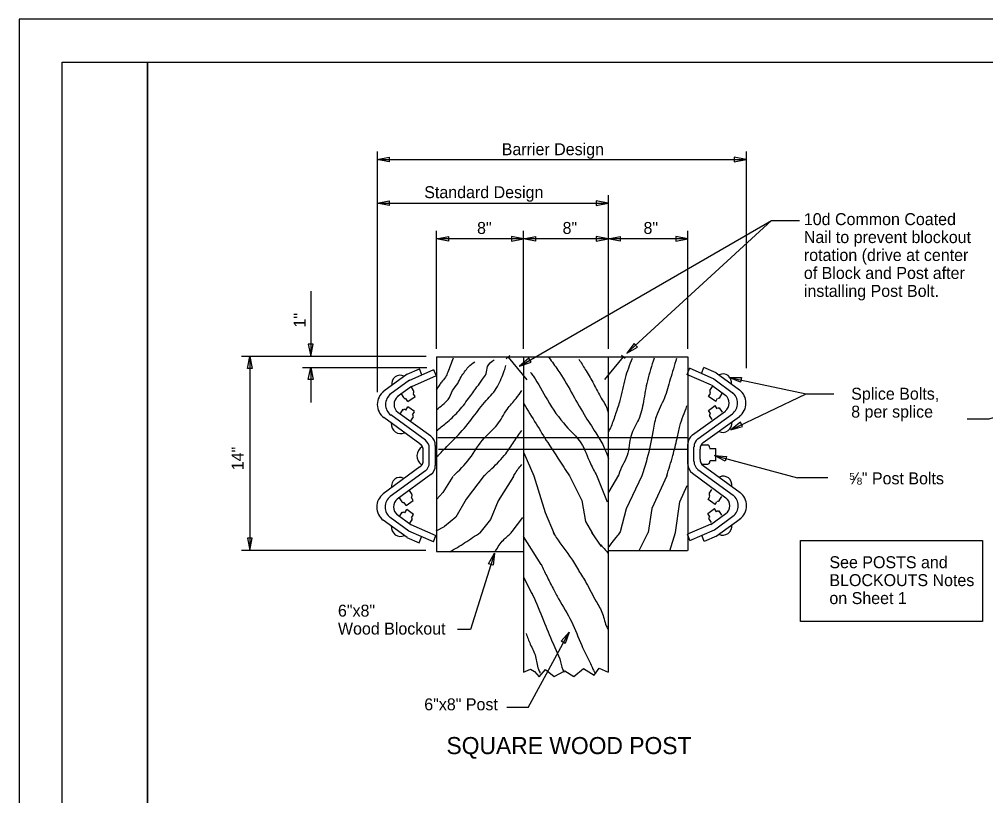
# Model space of a CAD drawing. Extents: x 0 to 34, y 0 to 22.
# Drawn here: x 0 to 11.31, y 12.91 to 22 of the extents above; entities that cross this region are included whole.
import ezdxf

# ---------------------------------------------------------------- set-up
doc = ezdxf.new("R2010")
doc.units = 0
for name, color, linetype in [('SH_Border', 7, 'Continuous'), ('SH_Cut_Line', 7, 'Continuous'), ('ST_Details', 7, 'Continuous'), ('ST_Text', 7, 'Continuous')]:
    doc.layers.add(name, color=color, linetype=linetype)

msp = doc.modelspace()

# ---------------------------------------------------------------- linework, layer by layer
at = {"layer": 'SH_Border'}
for points in [[(0.5, 21.5), (1.5, 21.5), (1.5, 0.5), (0.5, 0.5)], [(1.5, 21.5), (33.5, 21.5), (33.5, 0.5), (1.5, 0.5)]]:
    msp.add_lwpolyline(points, close=True, dxfattribs=at)
at = {"layer": 'SH_Cut_Line'}
msp.add_lwpolyline([(0, 0), (34, 0), (34, 22), (0, 22)], close=True, dxfattribs=at)
at = {"layer": 'ST_Details'}
for p, q in [((4.883, 18.048), (7.822, 18.048)), ((4.883, 18.048), (4.883, 15.767)), ((5.739, 18.063), (5.697, 18.026)), ((5.72, 18.044), (5.941, 17.779)), ((5.901, 18.048), (5.901, 14.354)), ((7.068, 18.049), (6.847, 17.784)), ((6.893, 18.048), (6.893, 14.354)), ((7.049, 18.068), (7.091, 18.031)), ((7.822, 18.048), (7.822, 15.78)), ((4.538, 17.845), (4.682, 17.908)), ((4.563, 17.772), (4.852, 17.898)), ((4.709, 17.838), (4.682, 17.907)), ((4.878, 17.828), (4.851, 17.897)), ((7.816, 17.843), (7.843, 17.913)), ((8.131, 17.787), (7.842, 17.914)), ((7.984, 17.853), (8.012, 17.922)), ((8.156, 17.86), (8.012, 17.923)), ((4.538, 17.845), (4.265, 17.645)), ((4.565, 17.773), (4.335, 17.605)), ((4.592, 17.701), (4.881, 17.828)), ((8.102, 17.717), (7.812, 17.843)), ((8.129, 17.789), (8.359, 17.62)), ((8.156, 17.86), (8.429, 17.66)), ((4.591, 17.701), (4.424, 17.579)), ((4.615, 17.653), (4.585, 17.7)), ((8.083, 17.655), (8.113, 17.702)), ((8.103, 17.716), (8.27, 17.594)), ((4.5, 17.57), (4.471, 17.616)), ((4.548, 17.524), (4.525, 17.56)), ((4.548, 17.524), (4.631, 17.583)), ((4.631, 17.583), (4.608, 17.618)), ((8.067, 17.585), (8.09, 17.62)), ((8.15, 17.526), (8.067, 17.585)), ((8.15, 17.526), (8.173, 17.562)), ((8.198, 17.572), (8.227, 17.618)), ((4.463, 17.385), (4.494, 17.435)), ((4.523, 17.425), (4.547, 17.464)), ((4.626, 17.406), (4.547, 17.463)), ((8.065, 17.421), (8.144, 17.478)), ((8.089, 17.383), (8.065, 17.42)), ((8.168, 17.44), (8.143, 17.479)), ((8.228, 17.4), (8.196, 17.45)), ((4.689, 17.028), (4.266, 17.336)), ((4.752, 17.073), (4.348, 17.367)), ((4.815, 17.118), (4.431, 17.398)), ((4.581, 17.299), (4.612, 17.347)), ((4.601, 17.367), (4.625, 17.405)), ((7.879, 17.133), (8.263, 17.413)), ((7.942, 17.088), (8.346, 17.382)), ((8.005, 17.043), (8.428, 17.351)), ((8.11, 17.314), (8.079, 17.362)), ((4.898, 17.102), (7.822, 17.102)), ((4.798, 16.807), (4.798, 16.98)), ((4.869, 16.777), (4.869, 17.01)), ((4.905, 16.966), (7.819, 16.966)), ((7.825, 16.792), (7.825, 17.025)), ((7.896, 16.822), (7.896, 16.995)), ((7.967, 16.851), (7.967, 16.966)), ((7.982, 17.016), (8.054, 17.016)), ((8.078, 16.975), (8.15, 16.975)), ((8.151, 16.835), (8.151, 16.974)), ((4.727, 16.836), (4.727, 16.95)), ((4.798, 16.888), (4.798, 16.899)), ((5.903, 16.922), (6.021, 16.653)), ((7.896, 16.903), (7.896, 16.914)), ((7.939, 16.964), (7.939, 16.964)), ((4.689, 16.759), (4.259, 16.444)), ((7.984, 16.791), (8.046, 16.791)), ((8.005, 16.774), (8.435, 16.459)), ((8.08, 16.835), (8.154, 16.835)), ((4.752, 16.714), (4.341, 16.413)), ((4.815, 16.669), (4.424, 16.382)), ((6.754, 16.662), (6.878, 16.351)), ((7.014, 16.662), (6.895, 16.465)), ((7.878, 16.685), (8.27, 16.397)), ((7.942, 16.73), (8.353, 16.428)), ((4.596, 16.435), (4.565, 16.482)), ((4.611, 16.365), (4.588, 16.4)), ((8.06, 16.378), (8.082, 16.414)), ((8.075, 16.448), (8.105, 16.495)), ((8.191, 16.366), (8.22, 16.411)), ((4.48, 16.352), (4.451, 16.398)), ((4.529, 16.306), (4.505, 16.342)), ((4.528, 16.306), (4.611, 16.365)), ((8.142, 16.32), (8.06, 16.378)), ((8.142, 16.319), (8.165, 16.355)), ((4.581, 16.082), (4.424, 16.197)), ((4.45, 16.18), (4.482, 16.23)), ((4.51, 16.22), (4.535, 16.259)), ((4.613, 16.201), (4.535, 16.259)), ((4.589, 16.163), (4.613, 16.2)), ((8.057, 16.214), (8.136, 16.272)), ((8.081, 16.176), (8.058, 16.213)), ((8.095, 16.085), (8.27, 16.212)), ((8.135, 16.023), (8.352, 16.181)), ((8.16, 16.233), (8.136, 16.272)), ((8.22, 16.193), (8.189, 16.243)), ((4.538, 15.931), (4.259, 16.135)), ((4.559, 16.007), (4.341, 16.166)), ((4.568, 16.094), (4.599, 16.142)), ((4.581, 16.083), (4.875, 15.955)), ((4.88, 16.01), (4.975, 16.061)), ((5.767, 16.001), (5.891, 16.167)), ((8.112, 16.098), (7.819, 15.97)), ((8.102, 16.107), (8.071, 16.155)), ((8.155, 15.947), (8.435, 16.15)), ((4.847, 15.881), (4.558, 16.008)), ((4.846, 15.881), (4.875, 15.955)), ((6.698, 15.992), (6.81, 15.827)), ((7.256, 15.78), (7.36, 15.992)), ((7.615, 15.776), (7.678, 15.992)), ((7.848, 15.897), (7.819, 15.97)), ((7.847, 15.897), (8.136, 16.023)), ((8.015, 15.885), (7.986, 15.958)), ((8.158, 15.947), (8.014, 15.885)), ((4.536, 15.932), (4.68, 15.869)), ((4.679, 15.87), (4.708, 15.942)), ((6.107, 15.617), (5.899, 15.943)), ((4.883, 15.767), (5.9, 15.767)), ((6.891, 15.78), (7.82, 15.78)), ((5.899, 15.469), (6, 15.276)), ((6.24, 14.705), (6.325, 14.51))]:
    msp.add_line(p, q, dxfattribs=at)
for points in [[(5.075, 16.645), (4.956, 16.461), (4.886, 16.382)], [(5.44, 16.657), (5.228, 16.382), (5.11, 16.171), (4.975, 16.061)], [(5.782, 16.647), (5.605, 16.36), (5.513, 16.145), (5.39, 15.988)], [(6.021, 16.653), (6.154, 16.224), (6.258, 15.974)], [(6.438, 16.653), (6.584, 16.364), (6.628, 16.119), (6.707, 15.979)], [(7.284, 16.653), (7.101, 16.268), (7.031, 15.997)], [(7.577, 16.653), (7.404, 16.272), (7.36, 15.992)], [(7.678, 15.992), (7.729, 16.351), (7.816, 16.54)], [(5.901, 14.354), (5.982, 14.392), (6.028, 14.362), (6.085, 14.3), (6.16, 14.388), (6.259, 14.305), (6.383, 14.37), (6.491, 14.305), (6.602, 14.397), (6.726, 14.322), (6.788, 14.401), (6.893, 14.354)]]:
    msp.add_lwpolyline(points, dxfattribs=at)
for centre, major_axis, start_param, end_param in [((4.458, 17.726), (0, -0.107), 2.687211, 4.851441), ((8.236, 17.741), (0, -0.107), 1.431744, 3.595974), ((4.366, 17.49), (0, -0.187), 3.747084, 5.680264), ((4.6, 17.64), (0, 0.0198), 3.70437, 5.352473), ((8.098, 17.642), (0, 0.0198), 0.930712, 2.578815), ((8.328, 17.506), (0, -0.187), 0.602921, 2.536101), ((4.428, 17.49), (0, -0.15), 3.747137, 5.680324), ((4.491, 17.491), (0, -0.112), 3.747102, 5.680297), ((4.513, 17.581), (0, -0.0195), 5.247458, 6.879592), ((8.185, 17.583), (0, -0.0195), 5.686779, 7.318912), ((8.203, 17.506), (0, -0.112), 0.602888, 2.536083), ((8.265, 17.506), (0, -0.15), 0.602861, 2.536048), ((4.507, 17.411), (0, 0.021), 5.452301, 7.118326), ((8.184, 17.426), (0, 0.021), 5.448045, 7.11407), ((4.592, 17.349), (0, 0.021), 4.196406, 5.73538), ((8.098, 17.364), (0, 0.021), 0.547805, 2.086779), ((4.461, 17.263), (0, -0.115), 4.640651, 6.714317), ((8.233, 17.278), (0, -0.115), 5.852054, 7.925719), ((4.745, 17.01), (0, 0.131), 4.712389, 5.680267), ((7.949, 17.025), (0, 0.131), 0.602918, 1.570796), ((8.002, 16.995), (0, 0.112), 0.602846, 1.570796), ((4.767, 16.888), (0, -0.12), 3.613765, 5.74142), ((4.639, 16.95), (0, 0.0937), 4.712389, 5.680377), ((4.692, 16.98), (0, 0.112), 4.712389, 5.68034), ((8.055, 16.966), (0, 0.0937), 0.602808, 1.570796), ((8.053, 16.986), (0, -0.0298), 2.729343, 3.43401), ((8.052, 16.985), (0, 0.03), 4.574534, 6.237266), ((8.053, 16.986), (0, -0.0298), 1.431351, 1.439211), ((4.639, 16.836), (0, -0.0937), 0.605563, 1.570796), ((4.692, 16.807), (0, -0.112), 0.605651, 1.570796), ((4.745, 16.777), (0, -0.131), 0.605566, 1.570796), ((7.949, 16.792), (0, -0.131), 4.712389, 5.677619), ((8.002, 16.822), (0, -0.112), 4.712389, 5.677535), ((8.055, 16.851), (0, -0.0937), 4.712389, 5.677623), ((8.051, 16.823), (0, -0.0326), 6.093782, 8.000338), ((4.455, 16.529), (0, -0.107), 2.687211, 4.851441), ((8.239, 16.544), (0, -0.107), 1.431744, 3.595974), ((4.359, 16.289), (0, -0.187), 3.747091, 5.68028), ((4.422, 16.289), (0, -0.15), 3.747115, 5.680355), ((4.58, 16.423), (0, 0.0198), 3.70437, 5.352473), ((8.091, 16.436), (0, 0.0198), 0.930712, 2.578815), ((8.272, 16.305), (0, -0.15), 0.602831, 2.53607), ((8.334, 16.305), (0, -0.187), 0.602905, 2.536094), ((4.484, 16.29), (0, -0.112), 3.747102, 5.680258), ((4.493, 16.363), (0, -0.0195), 5.247458, 6.879592), ((8.178, 16.376), (0, -0.0195), 5.686779, 7.318912), ((8.21, 16.305), (0, -0.112), 0.602927, 2.536083), ((4.494, 16.207), (0, 0.021), 5.452301, 7.118326), ((8.09, 16.157), (0, 0.021), 0.547805, 2.086779), ((8.176, 16.22), (0, 0.021), 5.448045, 7.11407), ((4.461, 16.06), (0, -0.115), 4.640651, 6.714317), ((4.58, 16.144), (0, 0.021), 4.196406, 5.73538), ((8.233, 16.075), (0, -0.115), 5.852054, 7.925719)]:
    msp.add_ellipse(centre, major_axis=major_axis, ratio=0.944544, start_param=start_param, end_param=end_param, dxfattribs=at)
for points in [[(5.078, 18.034), (5.015, 17.868), (4.986, 17.81), (4.942, 17.752), (4.913, 17.714), (4.88, 17.656)], [(4.884, 17.183), (4.993, 17.272), (5.131, 17.402), (5.258, 17.56), (5.356, 17.695), (5.422, 17.787), (5.462, 17.852), (5.48, 17.933), (5.557, 18.014)], [(4.884, 17.426), (4.953, 17.487), (5.019, 17.549), (5.069, 17.652), (5.131, 17.737), (5.171, 17.814), (5.211, 17.872), (5.255, 17.929), (5.33, 17.99)], [(6.198, 18.039), (6.304, 17.893), (6.46, 17.635), (6.609, 17.374), (6.747, 17.158), (6.838, 17.001), (6.896, 16.858)], [(6.548, 18.022), (6.623, 17.901), (6.711, 17.751), (6.801, 17.581), (6.878, 17.439), (6.889, 17.401)], [(7.173, 18.03), (7.09, 17.798), (7.028, 17.535), (6.979, 17.382), (6.925, 17.233), (6.892, 17.163)], [(7.43, 18.032), (7.351, 17.767), (7.305, 17.526), (7.247, 17.312), (7.16, 17.128), (7.115, 16.892), (7.016, 16.669), (7.013, 16.653)], [(7.692, 18.03), (7.619, 17.785), (7.549, 17.566), (7.454, 17.347), (7.413, 17.168), (7.346, 16.852), (7.284, 16.653)], [(4.888, 16.879), (4.986, 16.979), (5.138, 17.133), (5.313, 17.345), (5.465, 17.537), (5.596, 17.699), (5.64, 17.795), (5.676, 17.883), (5.693, 17.945)], [(5.984, 17.865), (6.013, 17.824), (6.18, 17.543), (6.398, 17.239), (6.573, 17.039), (6.685, 16.797), (6.759, 16.653)], [(5.08, 16.653), (5.269, 16.856), (5.44, 17.095), (5.593, 17.252), (5.709, 17.433), (5.814, 17.56), (5.883, 17.652)], [(5.904, 17.497), (6.049, 17.262), (6.184, 17.043), (6.373, 16.755), (6.438, 16.653)], [(7.577, 16.653), (7.648, 16.892), (7.698, 17.093), (7.731, 17.238), (7.814, 17.474)], [(5.436, 16.653), (5.531, 16.741), (5.694, 16.914), (5.789, 17.052), (5.883, 17.187)], [(5.782, 16.647), (5.796, 16.672), (5.88, 16.787)], [(5.037, 15.764), (5.215, 15.872), (5.395, 15.992)], [(5.574, 15.775), (5.665, 15.902), (5.756, 15.987), (5.772, 16.007)], [(6.247, 15.992), (6.284, 15.933), (6.462, 15.684), (6.554, 15.531)], [(7.031, 15.997), (6.999, 15.955), (6.933, 15.872), (6.9, 15.824)], [(6.806, 15.847), (6.856, 15.789), (6.892, 15.747)], [(6.106, 15.619), (6.172, 15.482), (6.247, 15.335)], [(6.546, 15.546), (6.635, 15.399), (6.751, 15.185), (6.826, 15.04), (6.879, 14.878), (6.892, 14.856)], [(5.997, 15.283), (6.007, 15.263), (6.135, 14.961), (6.244, 14.697)], [(6.248, 15.333), (6.309, 15.215), (6.462, 14.948), (6.582, 14.668), (6.673, 14.48), (6.714, 14.392), (6.743, 14.335)], [(5.93, 14.81), (5.98, 14.683), (6.042, 14.539), (6.075, 14.39), (6.096, 14.342)], [(6.325, 14.51), (6.362, 14.383), (6.375, 14.357)]]:
    msp.add_spline(points, degree=3, dxfattribs=at)
at = {"layer": 'ST_Text'}
for p, q in [((4.188, 20.453), (4.188, 18.032)), ((4.188, 20.359), (6.904, 20.359)), ((6.904, 20.359), (8.506, 20.359)), ((8.506, 20.453), (8.506, 17.917)), ((6.893, 19.942), (6.893, 19.396)), ((6.893, 19.942), (6.893, 18.142)), ((4.188, 19.847), (6.287, 19.847)), ((6.287, 19.847), (6.893, 19.847)), ((7.111, 18.089), (8.803, 19.644)), ((8.803, 19.644), (9.129, 19.644)), ((4.883, 18.142), (4.883, 19.523)), ((5.901, 18.142), (5.901, 19.523)), ((7.822, 18.142), (7.822, 19.523)), ((7.822, 19.429), (4.883, 19.429)), ((3.41, 18.816), (3.41, 18.055)), ((2.6, 18.055), (4.761, 18.055)), ((2.699, 18.05), (2.699, 17.328)), ((4.188, 18.032), (4.188, 17.901)), ((3.315, 17.924), (4.771, 17.924)), ((3.41, 17.924), (3.41, 17.515)), ((4.188, 17.901), (4.188, 17.635)), ((8.308, 17.807), (9.209, 17.614)), ((8.326, 17.194), (9.209, 17.614)), ((9.209, 17.614), (9.533, 17.614)), ((2.699, 17.328), (2.699, 15.785)), ((8.135, 16.891), (9.107, 16.631)), ((9.462, 16.631), (9.107, 16.631)), ((2.6, 15.785), (4.756, 15.785)), ((5.56, 15.749), (5.281, 14.855)), ((5.281, 14.855), (5.128, 14.855)), ((5.954, 13.943), (6.435, 14.825)), ((5.954, 13.943), (5.707, 13.943))]:
    msp.add_line(p, q, dxfattribs=at)
for points in [[(4.328, 20.331), (4.188, 20.359), (4.328, 20.387)], [(8.366, 20.331), (8.506, 20.359), (8.366, 20.387)], [(4.328, 19.819), (4.188, 19.847), (4.328, 19.875)], [(6.753, 19.819), (6.893, 19.847), (6.753, 19.875)], [(5.023, 19.401), (4.883, 19.429), (5.023, 19.457)], [(5.761, 19.401), (5.901, 19.429), (5.761, 19.457)], [(6.041, 19.401), (5.901, 19.429), (6.041, 19.457)], [(6.753, 19.401), (6.893, 19.429), (6.753, 19.457)], [(7.033, 19.401), (6.893, 19.429), (7.033, 19.457)], [(7.682, 19.401), (7.822, 19.429), (7.682, 19.457)], [(3.382, 18.195), (3.41, 18.055), (3.438, 18.195)], [(7.197, 18.203), (7.111, 18.089), (7.234, 18.162)], [(2.671, 17.91), (2.699, 18.05), (2.727, 17.91)], [(5.962, 18.033), (5.854, 17.939), (5.99, 17.984)], [(3.382, 17.784), (3.41, 17.924), (3.438, 17.784)], [(8.439, 17.751), (8.308, 17.807), (8.451, 17.806)], [(8.439, 17.281), (8.326, 17.194), (8.464, 17.231)], [(8.262, 16.826), (8.135, 16.891), (8.278, 16.88)], [(2.671, 15.925), (2.699, 15.785), (2.727, 15.925)], [(9.141, 15.897), (11.274, 15.897), (11.274, 14.948), (9.141, 14.948)], [(5.49, 15.624), (5.56, 15.749), (5.544, 15.607)], [(6.341, 14.718), (6.435, 14.825), (6.389, 14.69)]]:
    msp.add_lwpolyline(points, close=True, dxfattribs=at)
for points in [[(5.854, 17.939), (8.803, 19.644)], [(12.926, 17.807), (11.345, 17.318), (11.094, 17.318)]]:
    msp.add_lwpolyline(points, dxfattribs=at)

# ---------------------------------------------------------------- texts
for s, height, p in [('Barrier Design', 0.14, (5.646, 20.409)), ('Standard Design', 0.14, (4.739, 19.906)), ('10d Common Coated', 0.14, (9.182, 19.59)), ('  8"', 0.14, (5.253, 19.487)), ('  8"', 0.14, (6.254, 19.487)), ('  8"', 0.14, (7.201, 19.487)), ('Nail to prevent blockout', 0.14, (9.182, 19.38)), ('rotation (drive at center', 0.14, (9.182, 19.17)), ('of Block and Post after', 0.14, (9.182, 18.96)), ('installing Post Bolt.', 0.14, (9.182, 18.75)), ('Splice Bolts,', 0.14, (9.736, 17.546)), ('8 per splice', 0.14, (9.736, 17.336)), ('⅝" Post Bolts', 0.14, (9.704, 16.555)), ('See POSTS and', 0.14, (9.481, 15.573)), ('BLOCKOUTS Notes', 0.14, (9.481, 15.363)), ('on Sheet 1', 0.14, (9.481, 15.153)), ('6"x8"', 0.14, (3.729, 15.006)), ('Wood Blockout', 0.14, (3.729, 14.796)), ('6"x8" Post', 0.14, (4.739, 13.909)), ('SQUARE WOOD POST', 0.2, (4.999, 13.396))]:
    msp.add_text(s, height=height, dxfattribs=at).set_placement(p)
for s, p in [('1"', (3.35, 18.391)), ('14" ', (2.624, 16.72))]:
    msp.add_text(s, height=0.14, rotation=90, dxfattribs=at).set_placement(p)

doc.saveas('drawing.dxf')
